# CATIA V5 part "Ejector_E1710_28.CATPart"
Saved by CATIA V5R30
Part number: Vyhazovac_7x160_5
Nomenclature: E1710/7x160
Description: MEUSBURGER
Property "Material": "1.221"
Publications: "__DrillHole", "Base"
Bounding box of the stored display mesh (mm): x -5.992 to 5.992, y -5.992 to 5.992, z 0 to 152
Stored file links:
  E:\Bakalarka\Model\Forma_v7\Ejector_E1710_28.CATPart
  E:\dev\MoldDesign\intel_a\startup\components\MoldCatalog\Ejector\Meusburger\Ejector_E1710\TableE1710.txt
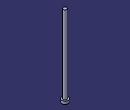
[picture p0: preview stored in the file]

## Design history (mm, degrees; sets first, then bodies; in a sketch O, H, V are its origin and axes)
Parameters
  Ref = "E1710/7x160" {design table}
  D1 = 7 mm {design table}
  D3 = 12 mm {design table}
  L = 160 mm {design table}
  L3 = 5 mm {design table}
  R = 0.5 mm {design table}
  k_d3 = 13 mm {design table}
  k_d1 = 7.2 mm {design table}
  k_F = 0.5 mm {design table}
  kl = 17 mm {design table}
  Mat = "1.221" {design table}
  HeatTreat = "ISO6751" {design table}
  Offset_Parting = 10 mm
  Anti_Rotation = "Normal"
  Anti_Rotation_D = 4 mm
  Anti_Rotation_D_Icut = 4 mm
  Add_Length_L = 1.3377 mm
  Add_Length_D3 = 0 mm
  SupplierRef = "Meusburger 2017"
  BmpRef = "F_MldEjectorD1"
  DrillHole_Length = 225 mm
  ValidationTest = false
  Anti_Rotation_D_min = 4 mm {= OffSet_D1 /2}
  Anti_Rotation_D_max = 5.925 mm {= D3/2-0.075mm}
  Anti_Rotation_D_ref = 4 mm {= Anti_Rotation_D}
  Anti_Rotation_D_Icut_ref = 4 mm {= Anti_Rotation_D_Icut}
  Anti_Rotation_Ref_Icut = 2.3246 mm
  Offset_L = 20 mm
  D = 7 mm {= D1}
  OffSet_D1 = 8 mm {= D1+2*R}
  OffSet_D3 = 13 mm {= D3+1mm}
  XG_Split = -54.5 mm
  YG_Split = -45 mm
  ZG_Split = -198 mm
  DirX_Split = 0 mm
  DirY_Split = 0 mm
  DirZ_Split = 1 mm
Set1 "BaseBody"
  Point1 "Base": (0, 0, 0)
  Plane1: type Offset, RefPlane xy-plane, Offset 225 {= DrillHole_Length}, reversed
  Sketch1 "Sketch.2" on xy-plane, origin (0, 0, 0), H (1, 0, 0), V (0, 1, 0)
    point P1 (-0.46, 1.1623)
    point P2 (0.46, 1.1623)
    construction line L1 (-0.46, 1.1623) -> (0.46, 1.1623)
    point P3 (0.46, -1.1623)
    line L2 (0.46, -1.1623) -> (0.46, 1.1623)
    point P4 (-0.46, -1.1623)
    construction line L3 (0.46, -1.1623) -> (-0.46, -1.1623)
    line L4 (-0.46, 1.1623) -> (-0.46, -1.1623)
    point P5 (-0.21, 1.1623)
    arc A1 centre (-0.21, 1.1623) radius 0.25 from (-0.21, 1.4123) to (-0.46, 1.1623) ccw
    point P7 (0.21, 1.1623)
    point P8 (0.21, 1.4123)
    arc A2 centre (0.21, 1.1623) radius 0.25 from (0.46, 1.1623) to (0.21, 1.4123) ccw
    line L5 (-0.21, 1.4123) -> (0.21, 1.4123)
    point P9 (-0.46, -1.1623)
    arc A3 centre (-0.21, -1.1623) radius 0.25 from (-0.46, -1.1623) to (-0.21, -1.4123) ccw
    point P11 (0.21, -1.4123)
    line L6 (-0.21, -1.4123) -> (0.21, -1.4123)
    point P12 (0.46, -1.1623)
    arc A4 centre (0.21, -1.1623) radius 0.25 from (0.21, -1.4123) to (0.46, -1.1623) ccw
    point P14 (-0.46, 1.1623)
    point P15 (-0.46, -1.1623)
    point P16 (0.46, 1.1623)
    point P17 (0.46, -1.1623)
    reference projected circle E1 centre (0, 0) radius 1.25 from edge [face of Shaft1 from Sketch2.L3 | face of Shaft1 from Sketch2.L4]
    reference projected circle E2 centre (0, 0) radius 1.25 from edge [face of Shaft1 from Sketch2.L3 | face of Shaft1 from Sketch2.L4]
    reference projected circle E3 centre (0, 0) radius 1.25 from edge [face of Shaft1 from Sketch2.L3 | face of Shaft1 from Sketch2.L4]
    reference projected circle E4 centre (0, 0) radius 1.25 from edge [face of Shaft1 from Sketch2.L3 | face of Shaft1 from Sketch2.L4]
    point P18 (-0.46, -1.1623)
    point P19 (-0.21, -1.4123)
    point P20 (0.21, -1.4123)
    point P21 (0.46, -1.1623)
    point P22 (-0.21, -1.4123)
    point P23 (0.21, -1.4123)
    distance P14 P15 = 2.3246 (reference)
    distance P16 P17 = 2.3246 (reference)
    distance L1 P14 = 0 (reference)
    radius A1 = 3.5
    distance L4 V = 4.01
    distance L2 V = 5.935
    distance L5 L6 = 12
    horizontal: L1 H, L3 H, L5 H
    vertical: L2 V, L4 V
    coincidence: P5 L1, P7 L1, P3 P12, P14 L4, P15 L4, P16 L2, P17 L2, P14 E1, P15 E2, P16 E3, P17 E4, P3 P21, P4 P18, P20 P23, P19 P22
    tangency: A1 L4, A2 L2, A2 L5, A1 L5
    symmetry: P1 P9 H, A1 A3 H, P8 P11 H, L5 L6 H, P2 P12 H, A2 A4 H
  DatumSurface1
Body1 "PartBody" (main body)
  Sketch2 "Sketch.1" on zx-plane, origin (0, 0, 0), H (-1, 0, 0), V (0, 0, 1)
    point P1 (0, 160)
    line L1 (3.5, 160) -> (0, 160)
    line L2 (3.5, 5) -> (3.5, 160)
    line L3 (6, 5) -> (3.5, 5)
    line L4 (6, 0) -> (6, 5)
    point P5 (0, 0)
    line L5 (0, 0) -> (6, 0)
    point P6 (0, 160)
    axis line L6 (0, 160) -> (0, 0)
    point P7 (0, 0)
    point P8 (3.5, 5)
    point P9 (3.5, 5)
    line L7 (0, 160) -> (0, 0)
    distance L5 L3 = 5 {= L3}
    distance L5 L1 = 160 {= L}
    distance L2 L6 = 3.5 {= D1 /2}
    distance L4 L6 = 6 {= D3 /2}
    coincidence: L6 P5, P1 L6, L5 H, L6 V, P7 O, P6 P1, P8 P9
    vertical: L2 V, L7 V
    horizontal: L1 H
  Shaft1 "Shaft.1": profile Sketch2, axis Sketch2.L6, angle 360
  Pocket1: profile face of Shaft1 from Sketch2.L1, direction along face of Shaft1 from Sketch2.L1 reversed, up to face of DatumSurface1
  Pocket2 "Pocket.1": profile Sketch1, direction (0, 0, 1), length 6, outer side, deactivated
  Pocket3 "Pocket.2": profile Sketch1, direction (0, 0, 1), length 6, outer side, deactivated
  Fillet1: radius 0.5 {= R}, on edge [face of Shaft1 from Sketch2.L2 | face of Shaft1 from Sketch2.L3]
Body2 "__DrillHole"
  Sketch3 "Sketch.3" on face of Shaft1, origin (0, 0, 0), H (1, 0, 0), V (0, -1, 0)
    point P1 (0, 0)
    reference projected point E1 (0, 0) from Point1
    coincidence: E1 P1
  Hole1 "Hole.1": placed by Sketch3, at (0, 0, 0) direction (0, 0, 1), diameter 8 {= OffSet_D1}, depth 140 {= L-Offset_L}
  Sketch4 "Sketch.4" on face of Shaft1, origin (0, 0, 0), H (1, 0, 0), V (0, -1, 0)
    point P1 (0, 0)
    reference projected point E1 (0, 0) from Point1
    coincidence: E1 P1
  Hole2 "Hole.2": placed by Sketch4, at (0, 0, 0) direction (0, 0, 1), diameter 7 {= D1}, depth 160 {= L}
  Sketch5 "Sketch.5" on face of Shaft1 from Sketch2.L3, origin (0, 0, 5), H (1, 0, 0), V (0, 1, 0)
    point P1 (0, 0)
    reference projected point E1 (0, 0) from Point1
    coincidence: E1 P1
  Hole3 "Hole.3": placed by Sketch5, at (0, 0, 5) direction (0, 0, -1), diameter 13 {= OffSet_D3}, depth 230 {= L3 +DrillHole_Length}
  Chamfer1: length 0.5 {= k_F}, angle 45, on edge [face of Hole1 | face of Hole3]
  Body3 "__Body.1"
    Pocket4 "Pocket.3": profile Sketch1, direction (0, 0, -1), length 225, opposite side length 5, deactivated
  Assemble1: tool Body3
  Chamfer2: length 0.5 {= k_F}, angle 45, on edge [start face of Pocket4 | face of Hole1], deactivated
  Body4 "__Body.2"
    Pocket5 "Pocket.4": profile Sketch1, direction (0, 0, -1), length 225, opposite side length 5, deactivated
  Assemble2: tool Body4
  Chamfer3: length 0.5 {= k_F}, angle 45, on edge [start face of Pocket5 | face of Hole1], deactivated
Current feature: Pocket1
Relations
  design table "TableE1710", configuration 278, drives Ref, D1, D3, L, L3, R, k_d3, k_d1, k_F, kl, Mat, HeatTreat
  Offset_L = 20mm (deactivated)
  rule "Cut_Head_rule":
    let sketch_cut (length)
    let PartBody_Pocket_Sketch (Boolean)
    let I_PartBody_Pocket (Boolean)
    let D_PartBody_Pocket (Boolean)
    let N_DrillHole_Hole (Boolean)
    let N_DrillHole_Hole_Sketch (Boolean)
    let I_DrillHole_Pocket (Boolean)
    let D_DrillHole_Pocket (Boolean)
    /* --------------------------------------------------------------------------------------*/
    if Anti_Rotation =="Normal"
    {
    	sketch_cut=Anti_Rotation_D_max
    	PartBody_Pocket_Sketch = false
    	I_PartBody_Pocket = false
    	D_PartBody_Pocket = false
    	N_DrillHole_Hole = true
    	N_DrillHole_Hole_Sketch = true
    	I_DrillHole_Pocket = false
    	D_DrillHole_Pocket = false
    	Chamfer1.Activity= true
    	Chamfer2.Activity= false
    	Chamfer3.Activity= false
    }
    if Anti_Rotation == "I_Cut"
    {
    	sketch_cut=Anti_Rotation_D_Icut_ref
    	PartBody_Pocket_Sketch = true
    	I_PartBody_Pocket = true
    	D_PartBody_Pocket = false
    	N_DrillHole_Hole = false
    	N_DrillHole_Hole_Sketch = false
    	I_DrillHole_Pocket = true
    	D_DrillHole_Pocket = false
    	Chamfer1.Activity= false
    	Chamfer2.Activity= true
    	Chamfer3.Activity= false
    }
    if Anti_Rotation =="D_Cut"
    {
    	sketch_cut=Anti_Rotation_D_max
    	PartBody_Pocket_Sketch = true
    	I_PartBody_Pocket = false
    	D_PartBody_Pocket = true
    	N_DrillHole_Hole = false
    	N_DrillHole_Hole_Sketch = false
    	I_DrillHole_Pocket = false
    	D_DrillHole_Pocket = true
    	Chamfer1.Activity= false
    	Chamfer2.Activity= false
    	Chamfer3.Activity= true
    }
    /* --------------------------------------------------------------------------------------*/
    Sketch1.distance(L2 V) = sketch_cut+0.01mm
    Sketch1.distance(L4 V) =Anti_Rotation_D_ref+0.01mm
    Sketch1.radius(A1) =D/2
    Pocket4.FirstLimit.Depth = DrillHole_Length
    Pocket5.FirstLimit.Depth = DrillHole_Length
    Pocket2.FirstLimit.Depth = L3+1mm
    Pocket3.FirstLimit.Depth = L3+1mm
    Pocket4.SecondLimit.Depth = L3
    Pocket5.SecondLimit.Depth =L3
    Pocket2.Activity = I_PartBody_Pocket
    Pocket3.Activity = D_PartBody_Pocket
    Sketch1.Activity =PartBody_Pocket_Sketch
    Hole3.Activity= N_DrillHole_Hole
    Sketch5.Activity = N_DrillHole_Hole_Sketch
    Pocket4.Activity = I_DrillHole_Pocket
    Pocket5.Activity  = D_DrillHole_Pocket
  rule "Anti_Rotation_Icut_constrain":
    let Ref1(length)
    let Ref2(length)
    let Ref3(length)
    let Diam1(length)
    let Diam2(length)
    let Add_Length_Lmin (length)
    Ref1=Sketch1.distance(P14 P15)
    Ref2=Sketch1.distance(P16 P17)
    Diam1=D
    Diam2=D3
    /* --------------------------------------------------------------------*/
    if Ref1 >Ref2
    	Anti_Rotation_Ref_Icut = Ref1
    else
    	Anti_Rotation_Ref_Icut  =Ref2
    Add_Length_D3 .InferiorRange=Anti_Rotation_Ref_Icut /2+Diam1/2 -Diam2/2
    if Add_Length_D3 .InferiorRange<0mm
    	Add_Length_D3 .InferiorRange=0mm
    if ValidationTest == "true"
    	Ref3   = 2*Add_Length_L +Anti_Rotation_Ref_Icut  +2*Diam1/2
    else
    	Ref3  =Diam2+2*Add_Length_D3
    if Ref3 <Diam2
    {
    	Ref3 =Diam2
    }
    /* --------------------------------------------------------------------*/
    Sketch1.distance(L5 L6) = Ref3
    Add_Length_L .InferiorRange=Diam2/2-Anti_Rotation_Ref_Icut/2-Diam1/2
    Add_Length_Lmin=Diam2/2-Anti_Rotation_Ref_Icut/2-Diam1/2
    if Add_Length_Lmin<0mm
    	Add_Length_L .InferiorRange=0mm
    else
    	Add_Length_L .InferiorRange=Add_Length_Lmin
